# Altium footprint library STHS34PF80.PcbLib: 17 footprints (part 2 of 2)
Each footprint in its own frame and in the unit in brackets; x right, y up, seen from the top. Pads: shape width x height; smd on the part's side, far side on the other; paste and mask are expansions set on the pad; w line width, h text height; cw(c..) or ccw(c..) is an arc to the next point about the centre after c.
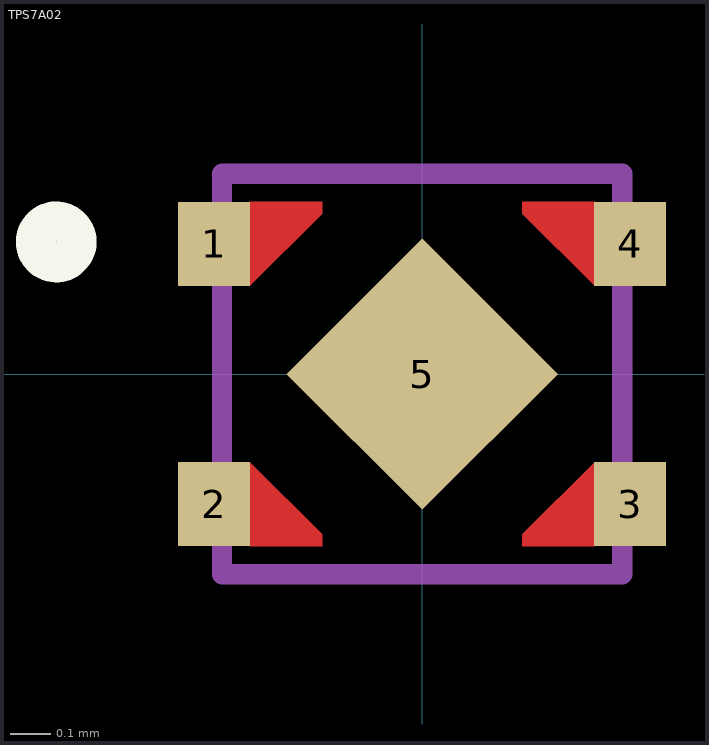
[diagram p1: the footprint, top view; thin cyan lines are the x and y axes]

## TPS7A02 [mm] "TPS7A02 LDO"
pads (5):
  rect 0.18x0.21 smd: 1(-0.52,0.325) 2(-0.52,-0.325) 3(0.52,-0.325) 4(0.52,0.325)
  rect 0.48x0.48 smd rot 45: 5(0,0)
Top Layer:
  region: -0.25,0.43 -0.25,0.4 -0.431,0.22 -0.431,0.43
  region: 0.25,-0.43 0.25,-0.4 0.431,-0.22 0.431,-0.43
  region: -0.431,-0.22 -0.25,-0.4 -0.25,-0.43 -0.431,-0.43
  region: 0.431,0.22 0.25,0.4 0.25,0.43 0.431,0.43
Top Overlay:
  circle w0.1: c-0.914,0.33 r0.051
Top Solder:
  rectangle: -0.33,-0.533 0.33,0.533
Mechanical 1:
  lines w0.051: -0.5,-0.5 -0.5,0.5 0.5,0.5 0.5,-0.5 -0.5,-0.5
  text "'.Designator'1" at -1.596,-0.241 h0.25
3D body "TPS7A0230_DQN0004A.stp": height 0.4, standoff -0.01, extent -0.5,-0.5 0.5,0.517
